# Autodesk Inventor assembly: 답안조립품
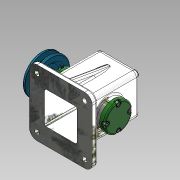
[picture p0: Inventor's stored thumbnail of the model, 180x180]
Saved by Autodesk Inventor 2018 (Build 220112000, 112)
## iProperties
Created: 2022-11
Part Number: 답안조립품
Material: 일반
Document SubType Name: Assembly
Designer: home
Author: home
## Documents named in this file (15)
- C:\Users\home\Desktop\721106V1003\답안조립품.iam
- C:\Users\home\Desktop\721106V1003\본체.ipt
- C:\Users\home\Desktop\721106V1003\앞커버.ipt
- C:\Users\home\Desktop\721106V1003\뒤커버.ipt
- C:\Users\home\Desktop\721106V1003\베어링 6201.ipt
- C:\Users\home\Desktop\721106V1003\편심축.ipt
- C:\Users\home\Desktop\721106V1003\링크.ipt
- C:\Users\home\Desktop\721106V1003\슬라이드.ipt
- C:\Users\home\Desktop\721106V1003\핀 5 x 18.ipt
- C:\Users\home\Desktop\721106V1003\고정핀 1.2 x 10.ipt
- C:\Users\home\Desktop\721106V1003\키 4 x 4 x 15.ipt
- C:\Users\home\Desktop\721106V1003\부시.ipt
- C:\Users\home\Desktop\721106V1003\V벨트풀리.ipt
- C:\Users\home\Desktop\721106V1003\멈춤나사 M3 x 8.ipt
- C:\Users\home\Desktop\721106V1003\볼트 M4 x 12.ipt
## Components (11 placed, 4 different names)
1. 핀 5 x 18:1
2. 고정핀 1.2 x 10:1
3. V벨트풀리:1
4. ISO 4762 M4 x 12:1
5. ISO 4762 M4 x 12:2
6. ISO 4762 M4 x 12:3
7. ISO 4762 M4 x 12:4
8. ISO 4762 M4 x 12:5
9. ISO 4762 M4 x 12:6
10. ISO 4762 M4 x 12:7
11. ISO 4762 M4 x 12:8
